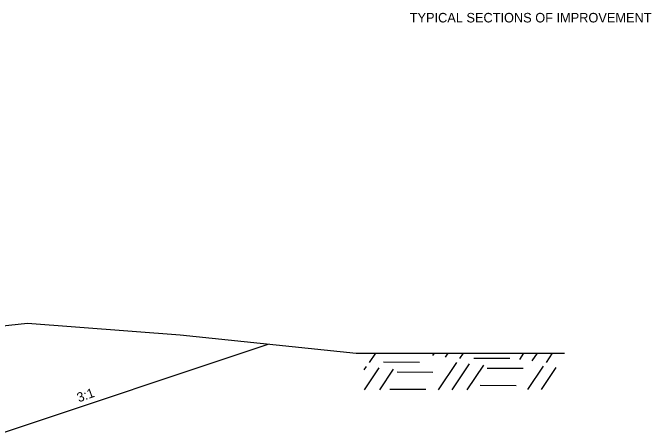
# Model space of a CAD drawing. Extents: x 1461846 to 1462006, y 1686171 to 1686805.
# Drawn here: x 1461961.96 to 1462002.1, y 1686241.48 to 1686267.98 of the extents above; entities that cross this region are included whole.
import ezdxf

# ---------------------------------------------------------------- set-up
doc = ezdxf.new("R2010")
doc.units = 0
for name, color, linetype in [('1', 7, 'Continuous'), ('19', 7, 'Continuous'), ('R_Draft', 7, 'Continuous')]:
    doc.layers.add(name, color=color, linetype=linetype)

msp = doc.modelspace()

# ---------------------------------------------------------------- linework, layer by layer
at = {"layer": '19'}
for p, q in [((1461983.55, 1686246.569), (1461996.659, 1686246.569)), ((1461984.392, 1686245.986), (1461984.784, 1686246.569)), ((1461988.378, 1686246.42), (1461988.484, 1686246.57)), ((1461989.172, 1686246.328), (1461989.338, 1686246.573)), ((1461990.068, 1686246.236), (1461990.294, 1686246.575)), ((1461993.832, 1686246.181), (1461994.094, 1686246.576)), ((1461994.627, 1686246.089), (1461994.958, 1686246.577)), ((1461995.522, 1686245.997), (1461995.903, 1686246.571)), ((1461990.955, 1686246.266), (1461993.216, 1686246.254)), ((1461985.281, 1686246.025), (1461987.541, 1686246.004)), ((1461988.73, 1686244.273), (1461989.882, 1686245.994)), ((1461989.584, 1686244.275), (1461990.677, 1686245.902)), ((1461990.54, 1686244.278), (1461991.572, 1686245.81)), ((1461994.34, 1686244.279), (1461995.336, 1686245.754)), ((1461984.053, 1686245.518), (1461984.206, 1686245.744)), ((1461984.075, 1686244.269), (1461985.001, 1686245.652)), ((1461985.03, 1686244.272), (1461985.897, 1686245.56)), ((1461986.121, 1686245.396), (1461988.381, 1686245.374)), ((1461991.785, 1686245.637), (1461994.056, 1686245.625)), ((1461995.194, 1686244.281), (1461996.131, 1686245.663)), ((1461991.343, 1686244.567), (1461993.603, 1686244.545)), ((1461985.668, 1686244.317), (1461987.939, 1686244.304))]:
    msp.add_line(p, q, dxfattribs=at)
at = {"layer": 'R_Draft'}
msp.add_line((1461961.046, 1686241.488), (1461978.028, 1686247.149), dxfattribs=at)
for points in [[(1461898.954, 1686241.476), (1461905.286, 1686243.936), (1461907.805, 1686244.527), (1461913.029, 1686245.425), (1461914.716, 1686245.68), (1461915.046, 1686246.481), (1461920.316, 1686246.387), (1461926.976, 1686246.462), (1461933.536, 1686246.367), (1461935.046, 1686246.521), (1461937.792, 1686245.91), (1461938.868, 1686245.881), (1461962.881, 1686248.455)], [(1461962.881, 1686248.455), (1461972.494, 1686247.73), (1461983.55, 1686246.569)]]:
    msp.add_lwpolyline(points, dxfattribs=at)

# ---------------------------------------------------------------- texts
at = {"layer": '1'}
msp.add_text('TYPICAL SECTIONS OF IMPROVEMENT', height=0.6, dxfattribs=at).set_placement((1461986.919, 1686267.373))
at = {"layer": '19'}
msp.add_text('3:1', height=0.59, rotation=19.5057, dxfattribs=at).set_placement((1461966.119, 1686243.478))

doc.saveas('drawing.dxf')
